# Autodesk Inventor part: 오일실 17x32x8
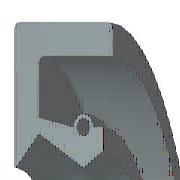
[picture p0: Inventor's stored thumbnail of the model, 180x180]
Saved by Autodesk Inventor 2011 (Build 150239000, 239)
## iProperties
IsCustomPart: 1
Company: 한국ATC센터
Created: 2014-07
Part Number: 오일실 17x32x8
Material: 고무
Description: 오일-실
Document SubType Name: Modeling
Standard: KS B 2804
Designer: KYOUNG IL JANG
Standards Organization: KS
Language: ko-KR
Size Designation: D - 17 32 8
Categories: <MemberInstance><Categories><Category DisplayName="샤프트 부품" InternalName="7f7aeb1f-a693-4053-b835-cee3144e0d98" Mnemonic="SHFT"><Category DisplayName="실링" Intern
Density: 0.93 g/cm^3
Author: KYOUNG IL JANG
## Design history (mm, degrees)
revolve "본체" stored, may be unused: angle "d17" = 90 deg
revolve "스프링1" stored, may be unused: angle "d18" = 90 deg
body "Solid1"
sketch "스케치1"
  geometry: L1 (0, 16)-(8, 16); L2 (8, 14.25)-(1.75, 14.25); L3 (1.75, 10.25)-(4.9, 8.5); L4 (4.9, 8.5)-(0, 8.5); L5 (0, 0)-(9.586, 0) reference; L6 (4.9, 8.5)-(6.3, 9.375); L7 (0, 18)-(0, -3) reference; L8 (-1.941, 0)-(11.507, 0) reference; L9 (4.2, 10.6)-(1.75, 11.21); L10 (1.75, 11.21)-(1.75, 14.25); L11 (0, 16)-(0, 8.588); L12 (4.9, 8.5)-(0, 8.5); L13 (1.75, 10.25)-(0.152, 8.528); L14 (8, 16)-(8, 14.25); L15 (5.6, 10.6)-(6.3, 10.6); L16 (6.3, 10.6)-(6.3, 9.375); C1 r 0.455 at (4.9, 10.6); A1 r 0.7 centre (4.9, 10.6) between (5.6, 10.6) and (4.2, 10.6); A2 r 0.088 centre (0.088, 8.588) between (0, 8.588) and (0.152, 8.528); 1 further point
  constraints: 28 end point, 5 horizontal alignment, 5 point on line, 4 point on circle, 4 vertical alignment, 3 centre point, 3 tangent, 2 collinear, 2 horizontal, 2 perpendicular, 1 coincident, 1 parallel
  dimensions: "d0" = 32 diameter of L1 L5 (= SD2); "d1" = 1.75 distance of L1.end L2.start (= SD); "d2" = 0.91 diameter of C1 (= SPDI); "d3" = 1.4 diameter of A1 (= SPDA); "d4" = 17 diameter of L3.end L5 (= NND); "d5" = 20.5 diameter of L3.start L5 (= TKDM); "d7" = 22.42 diameter of L9.end L5 (= TKDM + 0.24 x SWDT); "d8" = 1.75 distance between parallel lines of L11 L10 (= SD); "d9" = 4.9 distance from line of L11 C1.centre (= SPDST); "d10" = 21.2 diameter of C1.centre L5 (= HLDM); "d11" = 0.0875 radius of A2 (= 0.25 x LAB); "d12" = 6.3 distance between parallel lines of L11 L16 (= SDI); "d13" = 18.75 diameter of L6.end L5 (= ABDM); "d14" = 8 distance from line of L11 L1.end (= SWDT)
fillet "모깎기1" dims "d6" = 0.3 (= RR)
other parameters: "SD2" = 32 [user parameter; used in 1 equation term], "SWDT" = 8 [user parameter; used in 2 equation terms], "RR" = 0.3 [user parameter; used in 1 equation term], "SD" = 1.75 [user parameter; used in 2 equation terms], "NND" = 17 [user parameter; used in 1 equation term], "SPDA" = 1.4 [user parameter; used in 1 equation term], "SPDI" = 0.91 [user parameter; used in 1 equation term], "TKDM" = 20.5 [user parameter; used in 2 equation terms], "HLDM" = 21.2 [user parameter; used in 1 equation term], "ABDM" = 18.75 [user parameter; used in 1 equation term], "SDI" = 6.3 [user parameter; used in 1 equation term], "SPDST" = 4.9 [user parameter; used in 1 equation term], "LAB" = 0.35 [user parameter; used in 1 equation term], "d15" = 0, "d16" = 0, "d19" = 0
